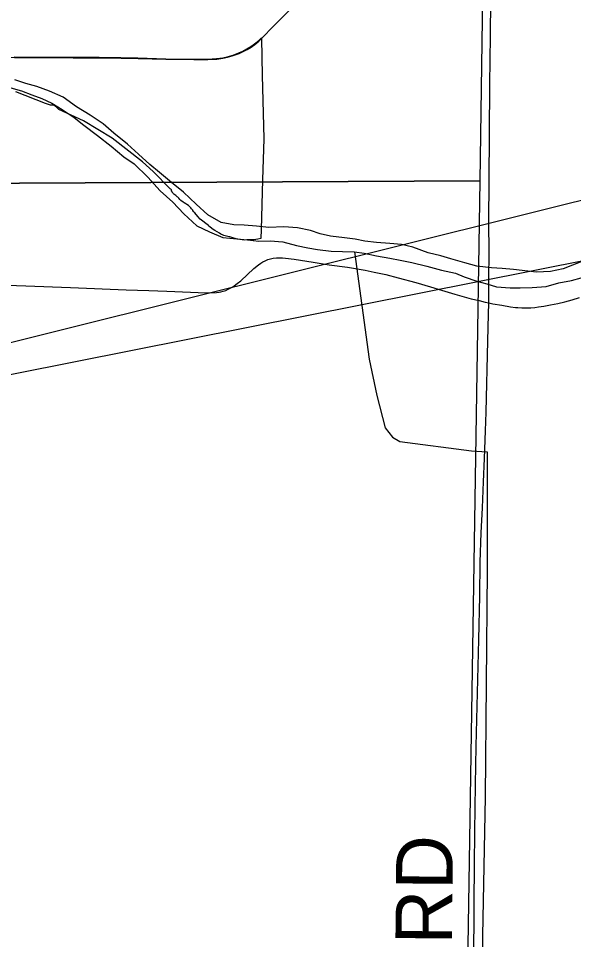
# Model space of a CAD drawing. Extents: x 0 to 34, y 0 to 22.
# Drawn here: x 5.615 to 6.172, y 16.776 to 17.701 of the extents above; entities that cross this region are included whole.
import ezdxf

# ---------------------------------------------------------------- set-up
doc = ezdxf.new("R2010")
doc.units = 0
for name, color, linetype in [('GM_X_Corporation', 7, 'Continuous'), ('GM_X_Major_River', 7, 'Continuous'), ('GM_X_Minor_River', 7, 'Continuous'), ('GM_X_Section', 7, 'Continuous'), ('GM_X_State_Route', 7, 'Continuous'), ('GM_X_Township_Road', 7, 'Continuous'), ('GM_X_Township_Road_Text', 7, 'Continuous'), ('SH_Text', 7, 'Continuous')]:
    doc.layers.add(name, color=color, linetype=linetype)

msp = doc.modelspace()

# ---------------------------------------------------------------- linework, layer by layer
at = {"layer": 'GM_X_Corporation'}
msp.add_lwpolyline([(5.61092, 17.66226), (5.66991, 17.66187), (5.69631, 17.66179), (5.71804, 17.66146), (5.73512, 17.66116), (5.76306, 17.66031), (5.79099, 17.65995), (5.80494, 17.66001), (5.81417, 17.66052), (5.82025, 17.66139), (5.82474, 17.66234), (5.83064, 17.66402), (5.83638, 17.66615), (5.84058, 17.66804), (5.84463, 17.6702), (5.84854, 17.67262), (5.85227, 17.6753), (5.85638, 17.67862), (5.85934, 17.68146), (5.85937, 17.66162), (5.85982, 17.64385), (5.86151, 17.58003), (5.86033, 17.5386), (5.85899, 17.48882), (5.85845, 17.47967), (5.85546, 17.4792), (5.85335, 17.4788), (5.85158, 17.47859), (5.84736, 17.47857), (5.84665, 17.47849), (5.84596, 17.47838), (5.84441, 17.47832), (5.84253, 17.47828), (5.84124, 17.47833), (5.83981, 17.47854), (5.8375, 17.47877), (5.8354, 17.47904), (5.83375, 17.47938), (5.83344, 17.47945), (5.83276, 17.47964), (5.83261, 17.47971), (5.83145, 17.48017), (5.82955, 17.48071), (5.8285, 17.48109), (5.82754, 17.48141), (5.82555, 17.48197), (5.82143, 17.48289), (5.82076, 17.48314), (5.81831, 17.48432), (5.81692, 17.48507), (5.81232, 17.48801), (5.81074, 17.48893), (5.80762, 17.49129), (5.8064, 17.49232), (5.80609, 17.4928), (5.79766, 17.49937), (5.7952, 17.50174), (5.79214, 17.50559), (5.79135, 17.50636), (5.79081, 17.50708), (5.79042, 17.50784), (5.79018, 17.50829), (5.78967, 17.50893), (5.7888, 17.50966), (5.78817, 17.51054), (5.786, 17.513), (5.78159, 17.51573), (5.78045, 17.5164), (5.77835, 17.51795), (5.77716, 17.51896), (5.77617, 17.52022), (5.77514, 17.52119), (5.77465, 17.5217), (5.77304, 17.52305), (5.77121, 17.52431), (5.77105, 17.52442), (5.77052, 17.52494), (5.77007, 17.52561), (5.76966, 17.52628), (5.76936, 17.52689), (5.76884, 17.52723), (5.76877, 17.52866), (5.76805, 17.52924), (5.76757, 17.52968), (5.75048, 17.54693), (5.7396, 17.55664), (5.70939, 17.58049), (5.68053, 17.59792), (5.65589, 17.60947), (5.65363, 17.61143), (5.65185, 17.61304), (5.64989, 17.61382), (5.64738, 17.61373), (5.64234, 17.61548), (5.6127, 17.6272)], dxfattribs=at)
at = {"layer": 'GM_X_Major_River'}
for points in [[(6.18408, 17.45802), (6.17146, 17.45302), (6.1619, 17.44945), (6.14934, 17.44672), (6.13511, 17.44607), (6.12667, 17.44695), (6.11228, 17.44876), (6.10094, 17.4498), (6.08998, 17.45044), (6.07524, 17.45194), (6.06321, 17.45527), (6.0493, 17.4594), (6.03914, 17.4623), (6.02634, 17.46527), (6.01096, 17.47096), (5.99967, 17.47389), (5.98796, 17.47493), (5.97472, 17.47563), (5.96302, 17.47705), (5.95322, 17.47919), (5.94265, 17.48058), (5.9283, 17.48207), (5.91814, 17.48459), (5.90837, 17.48787), (5.89518, 17.49046), (5.88158, 17.49155), (5.86641, 17.49078), (5.85433, 17.49222), (5.84186, 17.49328), (5.83126, 17.49353), (5.81882, 17.49573), (5.80538, 17.50365), (5.79352, 17.51419), (5.78095, 17.52626), (5.76869, 17.53604), (5.75683, 17.5462), (5.74717, 17.55402), (5.7357, 17.56454), (5.72459, 17.57468), (5.71085, 17.58564), (5.70009, 17.59501), (5.68706, 17.60368), (5.67363, 17.61197), (5.66024, 17.62178), (5.64651, 17.62779), (5.63361, 17.6323), (5.62271, 17.6356), (5.61144, 17.63929)], [(5.60745, 17.63104), (5.61836, 17.62811), (5.62849, 17.62407), (5.63862, 17.62041), (5.64873, 17.61561), (5.65917, 17.60929), (5.67109, 17.60141), (5.68075, 17.59358), (5.69451, 17.58338), (5.70825, 17.57242), (5.72086, 17.56187), (5.73129, 17.55478), (5.74497, 17.54155), (5.7575, 17.52758), (5.77009, 17.51627), (5.78117, 17.50462), (5.79412, 17.49254), (5.80685, 17.48654), (5.82034, 17.4809), (5.83432, 17.47942), (5.84527, 17.47839), (5.8566, 17.47698), (5.86797, 17.47746), (5.88044, 17.4764), (5.89436, 17.47265), (5.90567, 17.47047), (5.91547, 17.46872), (5.92907, 17.46725), (5.94041, 17.46659), (5.95252, 17.4663), (5.96234, 17.46492), (5.97477, 17.46235), (5.9881, 17.46001), (5.99852, 17.45797), (6.0102, 17.45579), (6.02526, 17.45201), (6.03992, 17.44786), (6.05386, 17.44487), (6.06272, 17.44138), (6.07526, 17.43713), (6.08541, 17.43423), (6.09518, 17.43134), (6.10879, 17.43025), (6.11902, 17.43038), (6.13076, 17.43048), (6.1448, 17.43165), (6.15776, 17.43513), (6.17032, 17.43748), (6.17997, 17.44031)]]:
    msp.add_lwpolyline(points, dxfattribs=at)
at = {"layer": 'GM_X_Minor_River'}
msp.add_lwpolyline([(5.95252, 17.4663), (5.96727, 17.35854), (5.97508, 17.3223), (5.98337, 17.28984), (5.9907, 17.28017), (5.99816, 17.27581), (6.06989, 17.26648), (6.08577, 17.26572), (6.08586, 17.14693), (6.08362, 16.91927), (6.08091, 16.77967), (6.08019, 16.67418), (6.07756, 16.56798), (6.0771, 16.51903), (6.07424, 16.46483), (6.07218, 16.38176), (6.07031, 16.27554), (6.06957, 16.15411), (6.06716, 16.01147)], dxfattribs=at)
at = {"layer": 'GM_X_Section'}
for points in [[(5.13129, 18.51595), (6.09233, 18.50979), (6.07847, 17.53783), (5.08739, 17.53257), (5.11234, 18.51615)], [(6.07847, 17.53783), (6.06277, 16.53445), (5.0695, 16.53641), (5.08739, 17.53257)]]:
    msp.add_lwpolyline(points, close=True, dxfattribs=at)
at = {"layer": 'GM_X_State_Route'}
for points in [[(5.85956, 17.6809), (5.87136, 17.69303), (5.88734, 17.70924), (5.90672, 17.72941), (5.93976, 17.7645), (5.9582, 17.78346), (5.97341, 17.799), (5.99343, 17.82071), (6.01291, 17.84084), (6.02917, 17.85755), (6.06115, 17.8915), (6.07086, 17.90155), (6.09066, 17.9225), (6.09719, 17.92942), (6.13092, 17.9652), (6.17647, 18.01367)], [(5.50439, 17.66274), (5.5475, 17.66218), (5.5863, 17.66178), (5.61114, 17.66171), (5.67013, 17.66132), (5.69653, 17.66123), (5.71827, 17.66091), (5.73535, 17.6606), (5.76328, 17.65976), (5.79122, 17.65939), (5.80516, 17.65946), (5.81439, 17.65996), (5.82047, 17.66083), (5.82496, 17.66178), (5.83086, 17.66347), (5.83661, 17.6656), (5.8408, 17.66749), (5.84486, 17.66964), (5.84877, 17.67206), (5.8525, 17.67475), (5.8566, 17.67806), (5.85956, 17.6809)]]:
    msp.add_lwpolyline(points, dxfattribs=at)
at = {"layer": 'GM_X_Township_Road'}
for points in [[(6.08729, 17.4152), (6.08746, 17.43751), (6.08758, 17.46703), (6.08755, 17.49501), (6.08803, 17.5836), (6.08849, 17.6349), (6.08923, 17.68307), (6.08974, 17.75611), (6.08967, 17.7903), (6.08956, 17.82916), (6.08964, 17.86492), (6.09015, 17.89912), (6.09058, 17.91933), (6.09066, 17.9225)], [(5.58466, 17.43365), (5.62257, 17.43235), (5.6673, 17.4306), (5.72321, 17.4283), (5.74621, 17.42747), (5.76421, 17.42682), (5.80375, 17.42541), (5.81395, 17.42569), (5.81654, 17.42586), (5.81851, 17.42619), (5.82073, 17.42685), (5.82324, 17.42776), (5.82567, 17.42879), (5.82785, 17.42994), (5.82986, 17.43109), (5.83179, 17.43231), (5.83491, 17.43447), (5.83835, 17.43725), (5.85153, 17.44961), (5.85628, 17.45346), (5.85844, 17.45512), (5.86061, 17.45652), (5.86279, 17.45755), (5.86559, 17.45862), (5.8683, 17.4594), (5.87106, 17.45998), (5.8741, 17.46035), (5.8774, 17.46043), (5.88023, 17.46035), (5.8834, 17.46012), (5.89199, 17.4591), (5.91095, 17.45612), (5.92721, 17.45345), (5.94546, 17.45092), (5.96331, 17.44788), (5.97236, 17.44616), (5.98395, 17.44361), (5.99629, 17.4404), (6.01415, 17.43548), (6.02887, 17.43129), (6.03998, 17.42792), (6.05339, 17.42389), (6.06984, 17.41921), (6.07773, 17.41741), (6.08366, 17.41601), (6.08729, 17.4152)], [(6.08729, 17.4152), (6.09139, 17.41429), (6.10036, 17.41281), (6.10924, 17.41133), (6.11427, 17.41066), (6.11648, 17.41051), (6.12051, 17.41027), (6.12528, 17.4101), (6.12964, 17.41035), (6.13367, 17.4106), (6.13729, 17.41109), (6.14247, 17.41184), (6.14938, 17.41316), (6.1567, 17.41463), (6.16369, 17.41629), (6.17101, 17.41834), (6.17841, 17.42057)], [(6.06954, 16.53012), (6.06968, 16.54252), (6.0703, 16.58758), (6.07175, 16.71502), (6.07215, 16.74766), (6.07259, 16.79272), (6.07274, 16.81294), (6.07313, 16.85023), (6.07351, 16.88443), (6.07412, 16.93106), (6.07471, 16.96991), (6.07731, 17.07713), (6.07821, 17.12063), (6.07884, 17.15483), (6.07981, 17.18436), (6.08096, 17.2092), (6.08211, 17.23559), (6.08298, 17.25889), (6.08414, 17.28683), (6.08467, 17.30546), (6.08647, 17.37694), (6.08719, 17.40334), (6.08729, 17.4152)]]:
    msp.add_lwpolyline(points, dxfattribs=at)
at = {"layer": 'SH_Text'}
msp.add_lwpolyline([(9.31108, 18.29898), (4.97713, 17.21812), (9.31108, 18.08015)], close=True, dxfattribs=at)

# ---------------------------------------------------------------- texts
at = {"layer": 'GM_X_Township_Road_Text'}
msp.add_text('RD', height=0.056818, rotation=89.50966, dxfattribs=at).set_placement((6.05043, 16.7707))

doc.saveas('drawing.dxf')
